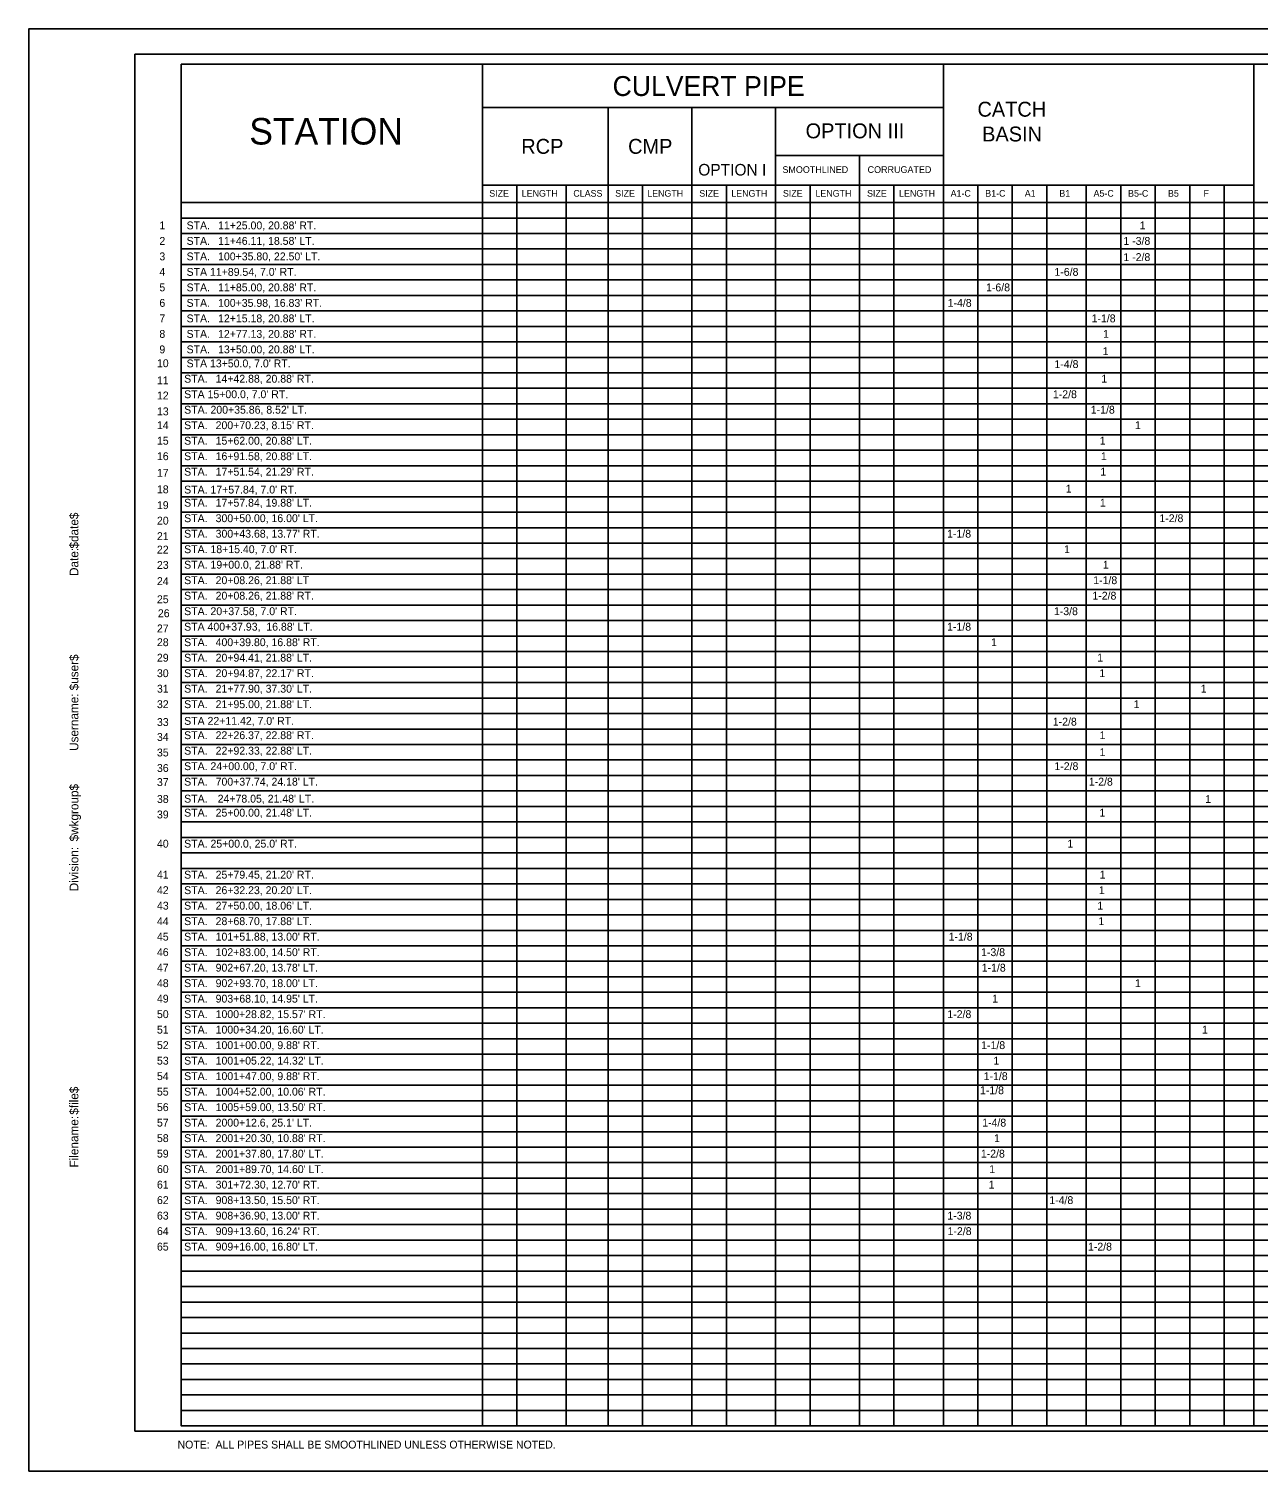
# Model space of a CAD drawing. Extents: x -0.13 to 2.7, y -0.05 to 1.78.
# Drawn here: x -0.135 to 1.428, y -0.051 to 1.782 of the extents above; entities that cross this region are included whole.
import ezdxf

# ---------------------------------------------------------------- set-up
doc = ezdxf.new("R2010")
doc.units = 0
for name, color, linetype in [('ANNOTATION', 7, 'Continuous'), ('BORDER', 7, 'Continuous'), ('PLOT BOUNDARY', 7, 'Continuous')]:
    doc.layers.add(name, color=color, linetype=linetype)

msp = doc.modelspace()

# ---------------------------------------------------------------- linework, layer by layer
at = {"layer": 'BORDER'}
for p, q in [((2.6667, 1.75), (0, 1.75)), ((0, 1.75), (0, 0)), ((0.4417, 1.6825), (0.4417, 1.7373)), ((1.0278, 1.6825), (1.0278, 1.7373)), ((1.4226, 0.0065), (1.4226, 1.7373)), ((0.4417, 1.6214), (0.4417, 1.6825)), ((0.4417, 1.6825), (0.4855, 1.6825)), ((0.4855, 1.6825), (0.5482, 1.6825)), ((0.5482, 1.6825), (0.6015, 1.6825)), ((0.6015, 1.6214), (0.6015, 1.6825)), ((0.6015, 1.6825), (0.6454, 1.6825)), ((0.6454, 1.6825), (0.7081, 1.6825)), ((0.7081, 1.6214), (0.7081, 1.6825)), ((0.7081, 1.6825), (0.7519, 1.6825)), ((0.7519, 1.6825), (0.8585, 1.6825)), ((0.8146, 1.5836), (0.8146, 1.6825)), ((0.8585, 1.6825), (1.0278, 1.6825)), ((1.0278, 1.6214), (1.0278, 1.6825)), ((0.4417, 1.5836), (0.4417, 1.6214)), ((0.6015, 1.5836), (0.6015, 1.6214)), ((0.7081, 1.5836), (0.7081, 1.6214)), ((0.8146, 1.6214), (0.8585, 1.6214)), ((0.8585, 1.6214), (0.965, 1.6214)), ((0.9212, 1.5616), (0.9212, 1.6214)), ((0.965, 1.6214), (1.0278, 1.6214)), ((1.0278, 1.5836), (1.0278, 1.6214)), ((0.4417, 1.5616), (0.4417, 1.5836)), ((0.4417, 1.5836), (0.4855, 1.5836)), ((0.4855, 1.5616), (0.4855, 1.5836)), ((0.4855, 1.5836), (0.5482, 1.5836)), ((0.5482, 1.5616), (0.5482, 1.5836)), ((0.5482, 1.5836), (0.6015, 1.5836)), ((0.6015, 1.5616), (0.6015, 1.5836)), ((0.6015, 1.5836), (0.6454, 1.5836)), ((0.6454, 1.5616), (0.6454, 1.5836)), ((0.6454, 1.5836), (0.7081, 1.5836)), ((0.7081, 1.5616), (0.7081, 1.5836)), ((0.7081, 1.5836), (0.7519, 1.5836)), ((0.7519, 1.5616), (0.7519, 1.5836)), ((0.7519, 1.5836), (0.8146, 1.5836)), ((0.8146, 1.5616), (0.8146, 1.5836)), ((0.8146, 1.5836), (0.8585, 1.5836)), ((0.8585, 1.5616), (0.8585, 1.5836)), ((0.8585, 1.5836), (0.9212, 1.5836)), ((0.9212, 1.5836), (0.965, 1.5836)), ((0.965, 1.5616), (0.965, 1.5836)), ((0.965, 1.5836), (1.0278, 1.5836)), ((1.0278, 1.5616), (1.0278, 1.5836)), ((1.0278, 1.5836), (1.0716, 1.5836)), ((1.0716, 1.5616), (1.0716, 1.5836)), ((1.0716, 1.5836), (1.1155, 1.5836)), ((1.1155, 1.5616), (1.1155, 1.5836)), ((1.1155, 1.5836), (1.1594, 1.5836)), ((1.1594, 1.5616), (1.1594, 1.5836)), ((1.1594, 1.5836), (1.1844, 1.5836)), ((1.1844, 1.5836), (1.2095, 1.5836)), ((1.2095, 1.5616), (1.2095, 1.5836)), ((1.2095, 1.5836), (1.2533, 1.5836)), ((1.2533, 1.5616), (1.2533, 1.5836)), ((1.2533, 1.5836), (1.2972, 1.5836)), ((1.2972, 1.5616), (1.2972, 1.5836)), ((1.2972, 1.5836), (1.4226, 1.5836)), ((1.3411, 1.5616), (1.3411, 1.5836)), ((1.385, 1.5616), (1.385, 1.5836)), ((0.4417, 1.5616), (0.4417, 0.0065)), ((0.4855, 1.5616), (0.4855, 0.0065)), ((0.5482, 1.5616), (0.5482, 0.0065)), ((0.6015, 1.5616), (0.6015, 0.0065)), ((0.6454, 1.5616), (0.6454, 0.0065)), ((0.7081, 1.5616), (0.7081, 0.0065)), ((0.7519, 1.5616), (0.7519, 0.0065)), ((0.8146, 1.5616), (0.8146, 0.0065)), ((0.8585, 1.5616), (0.8585, 0.0065)), ((0.9212, 1.5616), (0.9212, 0.0065)), ((0.965, 1.5616), (0.965, 0.0065)), ((1.0278, 1.5616), (1.0278, 0.0065)), ((1.0716, 1.5616), (1.0716, 0.0065)), ((1.1155, 1.5616), (1.1155, 0.0065)), ((1.1594, 1.5616), (1.1594, 0.0065)), ((1.2095, 1.5616), (1.2095, 0.0065)), ((1.2533, 1.5616), (1.2533, 0.0065)), ((1.2972, 1.5616), (1.2972, 0.0065)), ((1.3411, 1.5616), (1.3411, 0.0065)), ((1.385, 1.5616), (1.385, 0.0065)), ((0.0589, 1.5419), (2.4434, 1.5419)), ((0.0589, 1.5223), (2.4434, 1.5223)), ((0.0589, 1.5026), (2.4434, 1.5026)), ((0.0589, 1.4829), (2.4434, 1.4829)), ((0.0589, 1.4632), (2.4434, 1.4632)), ((0.0589, 1.4435), (2.4434, 1.4435)), ((0.0589, 1.4238), (2.4434, 1.4238)), ((0.0589, 1.4041), (2.4434, 1.4041)), ((0.0589, 1.3845), (2.4434, 1.3845)), ((0.0589, 1.3648), (2.4434, 1.3648)), ((0.0589, 1.3451), (2.4434, 1.3451)), ((0.0589, 1.3254), (2.4434, 1.3254)), ((0.0589, 1.3057), (2.4434, 1.3057)), ((0.0589, 1.286), (2.4434, 1.286)), ((0.0589, 1.2664), (2.4434, 1.2664)), ((0.0589, 1.2467), (2.4434, 1.2467)), ((0.0589, 1.227), (2.4434, 1.227)), ((0.0589, 1.2073), (2.4434, 1.2073)), ((0.0589, 1.1876), (2.4434, 1.1876)), ((0.0589, 1.1679), (2.4434, 1.1679)), ((0.0589, 1.1482), (2.4434, 1.1482)), ((0.0589, 1.1286), (2.4434, 1.1286)), ((0.0589, 1.1089), (2.4434, 1.1089)), ((0.0589, 1.0892), (2.4434, 1.0892)), ((0.0589, 1.0695), (2.4434, 1.0695)), ((0.0589, 1.0498), (2.4434, 1.0498)), ((0.0589, 1.0301), (2.4434, 1.0301)), ((0.0589, 1.0104), (2.4434, 1.0104)), ((0.0589, 0.9908), (2.4434, 0.9908)), ((0.0589, 0.9711), (2.4434, 0.9711)), ((0.0589, 0.9514), (2.4434, 0.9514)), ((0.0589, 0.9317), (2.4434, 0.9317)), ((0.0589, 0.912), (2.4434, 0.912)), ((0.0589, 0.8923), (2.4434, 0.8923)), ((0.0589, 0.8727), (2.4434, 0.8727)), ((0.0589, 0.853), (2.4434, 0.853)), ((0.0589, 0.8333), (2.4434, 0.8333)), ((0.0589, 0.8136), (2.4434, 0.8136)), ((0.0589, 0.7939), (2.4434, 0.7939)), ((0.0589, 0.7742), (2.4434, 0.7742)), ((0.0589, 0.7545), (2.4434, 0.7545)), ((0.0589, 0.7349), (2.4434, 0.7349)), ((0.0589, 0.7152), (2.4434, 0.7152)), ((0.0589, 0.6955), (2.4434, 0.6955)), ((0.0589, 0.6758), (2.4434, 0.6758)), ((0.0589, 0.6561), (2.4434, 0.6561)), ((0.0589, 0.6364), (2.4434, 0.6364)), ((0.0589, 0.6167), (2.4434, 0.6167)), ((0.0589, 0.5971), (2.4434, 0.5971)), ((0.0589, 0.5774), (2.4434, 0.5774)), ((0.0589, 0.5577), (2.4434, 0.5577)), ((0.0589, 0.538), (2.4434, 0.538)), ((0.0589, 0.5183), (2.4434, 0.5183)), ((0.0589, 0.4986), (2.4434, 0.4986)), ((0.0589, 0.479), (2.4434, 0.479)), ((0.0589, 0.4593), (2.4434, 0.4593)), ((0.0589, 0.4396), (2.4434, 0.4396)), ((0.0589, 0.4199), (2.4434, 0.4199)), ((0.0589, 0.4002), (2.4434, 0.4002)), ((0.0589, 0.3805), (2.4434, 0.3805)), ((0.0589, 0.3608), (2.4434, 0.3608)), ((0.0589, 0.3412), (2.4434, 0.3412)), ((0.0589, 0.3215), (2.4434, 0.3215)), ((0.0589, 0.3018), (2.4434, 0.3018)), ((0.0589, 0.2821), (2.4434, 0.2821)), ((0.0589, 0.2624), (2.4434, 0.2624)), ((0.0589, 0.2427), (2.4434, 0.2427)), ((0.0589, 0.223), (2.4434, 0.223)), ((0.0589, 0.2034), (2.4434, 0.2034)), ((0.0589, 0.1837), (2.4434, 0.1837)), ((0.0589, 0.164), (2.4434, 0.164)), ((0.0589, 0.1443), (2.4434, 0.1443)), ((0.0589, 0.1246), (2.4434, 0.1246)), ((0.0589, 0.1049), (2.4434, 0.1049)), ((0.0589, 0.0853), (2.4434, 0.0853)), ((0.0589, 0.0656), (2.4434, 0.0656)), ((0.0589, 0.0459), (2.4434, 0.0459)), ((0.0589, 0.0262), (2.4434, 0.0262)), ((0, 0), (2.6667, 0)), ((0.0589, 0.0065), (2.3003, 0.0065))]:
    msp.add_line(p, q, dxfattribs=at)
msp.add_lwpolyline([(0.0589, 1.7373), (2.4434, 1.7373), (2.4434, 1.5616), (0.0589, 1.5616)], close=True, dxfattribs=at)
msp.add_lwpolyline([(0.0589, 1.5616), (0.0589, 0.0065), (2.4434, 0.0065), (2.4434, 1.5616)], dxfattribs=at)
at = {"layer": 'PLOT BOUNDARY'}
msp.add_lwpolyline([(-0.1349, -0.051), (2.6984, -0.051), (2.6984, 1.7823), (-0.1349, 1.7823)], close=True, dxfattribs=at)

# ---------------------------------------------------------------- texts
at = {"layer": 'ANNOTATION'}
for s, p in [('1', (0.0311, 1.5275)), ('STA.', (0.0657, 1.5275)), ("11+25.00, 20.88' RT.", (0.1057, 1.5275)), ('1', (1.2774, 1.5275)), ('2', (0.0311, 1.5078)), ('STA.', (0.0657, 1.5078)), ("11+46.11, 18.58' LT.", (0.1057, 1.5078)), ('1 -3/8', (1.2567, 1.5078)), ('3', (0.0311, 1.4881)), ('STA.', (0.0657, 1.4881)), ("100+35.80, 22.50' LT.", (0.1057, 1.4881)), ('1 -2/8', (1.2567, 1.4872)), ('4', (0.0311, 1.4684)), ("STA 11+89.54, 7.0' RT.", (0.0657, 1.4684)), ('1-6/8', (1.1691, 1.4684)), ('5', (0.0311, 1.4487)), ('STA.', (0.0657, 1.4487)), ("11+85.00, 20.88' RT.", (0.1057, 1.4487)), ('1-6/8', (1.0821, 1.4487)), ('6', (0.0311, 1.429)), ('STA.', (0.0657, 1.429)), ("100+35.98, 16.83' RT.", (0.1057, 1.429)), ('1-4/8', (1.0333, 1.429)), ('7', (0.0311, 1.4093)), ('STA.', (0.0657, 1.4093)), ("12+15.18, 20.88' LT.", (0.1057, 1.4093)), ('1-1/8', (1.2163, 1.4093)), ('8', (0.0311, 1.3896)), ('STA.', (0.0657, 1.3896)), ("12+77.13, 20.88' RT.", (0.1057, 1.3896)), ('1', (1.2309, 1.3896)), ('9', (0.0311, 1.3699)), ('STA.', (0.0657, 1.3699)), ("13+50.00, 20.88' LT.", (0.1057, 1.3699)), ('1', (1.2304, 1.3677)), ('10', (0.028, 1.3523)), ("STA 13+50.0, 7.0' RT.", (0.0657, 1.3521)), ('1-4/8', (1.1691, 1.3512)), ('11', (0.028, 1.3305)), ('STA.', (0.0626, 1.3326)), ("14+42.88, 20.88' RT.", (0.1026, 1.3326)), ('1', (1.2286, 1.3326)), ('12', (0.028, 1.3113)), ("STA 15+00.0, 7.0' RT.", (0.0626, 1.3129)), ('1-2/8', (1.1671, 1.3129)), ("STA. 200+35.86, 8.52' LT.", (0.0626, 1.2932)), ('1-1/8', (1.2153, 1.2932)), ('13', (0.028, 1.2911)), ('14', (0.028, 1.2735)), ('STA.', (0.0626, 1.2735)), ("200+70.23, 8.15' RT.", (0.1026, 1.2735)), ('1', (1.2715, 1.2735)), ('15', (0.028, 1.2538)), ('STA.', (0.0626, 1.2538)), ("15+62.00, 20.88' LT.", (0.1026, 1.2538)), ('1', (1.2266, 1.2538)), ('16', (0.028, 1.2341)), ('STA.', (0.0626, 1.2341)), ("16+91.58, 20.88' LT.", (0.1026, 1.2341)), ('1', (1.2281, 1.2341)), ('17', (0.028, 1.213)), ('STA.', (0.0626, 1.2144)), ("17+51.54, 21.29' RT.", (0.1026, 1.2144)), ('1', (1.2274, 1.2144)), ('18', (0.028, 1.192)), ("STA. 17+57.84, 7.0' RT.", (0.0626, 1.1917)), ('1', (1.1834, 1.1928)), ('19', (0.028, 1.1719)), ('STA.', (0.0626, 1.175)), ("17+57.84, 19.88' LT.", (0.1026, 1.175)), ('1', (1.2268, 1.175)), ('20', (0.028, 1.1522)), ('STA.', (0.0626, 1.1553)), ("300+50.00, 16.00' LT.", (0.1026, 1.1553)), ('1-2/8', (1.3025, 1.1553)), ('21', (0.028, 1.1325)), ('STA.', (0.0626, 1.1356)), ("300+43.68, 13.77' RT.", (0.1026, 1.1356)), ('1-1/8', (1.0326, 1.1356)), ('22', (0.028, 1.1154)), ("STA. 18+15.40, 7.0' RT.", (0.0626, 1.1159)), ('1', (1.1813, 1.1159)), ('23', (0.028, 1.0959)), ("STA. 19+00.0, 21.88' RT.", (0.0626, 1.0962)), ('1', (1.2306, 1.0962)), ('24', (0.028, 1.0753)), ('STA.', (0.0626, 1.0765)), ("20+08.26, 21.88' LT", (0.1026, 1.0765)), ('1-1/8', (1.2184, 1.0765)), ('STA.', (0.0626, 1.0568)), ("20+08.26, 21.88' RT.", (0.1026, 1.0568)), ('1-2/8', (1.2173, 1.0568)), ('25', (0.028, 1.0523)), ("STA. 20+37.58, 7.0' RT.", (0.0626, 1.0371)), ('1-3/8', (1.1684, 1.0371)), ('26', (0.0292, 1.0345)), ("STA 400+37.93,  16.88' LT.", (0.0626, 1.0174)), ('1-1/8', (1.0326, 1.0174)), ('27', (0.028, 1.0152)), ('28', (0.028, 0.9977)), ('STA.', (0.0626, 0.9977)), ("400+39.80, 16.88' RT.", (0.1026, 0.9977)), ('1', (1.0885, 0.9977)), ('29', (0.028, 0.978)), ('STA.', (0.0626, 0.978)), ("20+94.41, 21.88' LT.", (0.1026, 0.978)), ('1', (1.2234, 0.978)), ('30', (0.028, 0.9583)), ('STA.', (0.0626, 0.9583)), ("20+94.87, 22.17' RT.", (0.1026, 0.9583)), ('1', (1.2261, 0.9583)), ('31', (0.028, 0.9386)), ('STA.', (0.0626, 0.9386)), ("21+77.90, 37.30' LT.", (0.1026, 0.9386)), ('1', (1.355, 0.9386)), ('32', (0.028, 0.9189)), ('STA.', (0.0626, 0.9189)), ("21+95.00, 21.88' LT.", (0.1026, 0.9189)), ('1', (1.2698, 0.9189)), ('33', (0.028, 0.8962)), ("STA 22+11.42, 7.0' RT.", (0.0626, 0.8977)), ('1-2/8', (1.167, 0.8967)), ('34', (0.028, 0.8772)), ('STA.', (0.0626, 0.8795)), ("22+26.37, 22.88' RT.", (0.1026, 0.8795)), ('1', (1.2264, 0.8795)), ('35', (0.028, 0.8575)), ('STA.', (0.0626, 0.8598)), ("22+92.33, 22.88' LT.", (0.1026, 0.8598)), ('1', (1.2264, 0.8579)), ('36', (0.028, 0.8378)), ("STA. 24+00.00, 7.0' RT.", (0.0626, 0.8401)), ('1-2/8', (1.169, 0.8401)), ('37', (0.028, 0.8199)), ('STA.', (0.0626, 0.8204)), ("700+37.74, 24.18' LT.", (0.1026, 0.8204)), ('1-2/8', (1.2128, 0.8204)), ('38', (0.028, 0.7984)), ('STA.', (0.0626, 0.7988)), ("24+78.05, 21.48' LT.", (0.1052, 0.7988)), ('1', (1.3607, 0.7983)), ('39', (0.028, 0.7787)), ('STA.', (0.0626, 0.781)), ("25+00.00, 21.48' LT.", (0.1026, 0.781)), ('1', (1.2262, 0.781)), ('40', (0.028, 0.7416)), ("STA. 25+00.0, 25.0' RT.", (0.0626, 0.7416)), ('1', (1.1855, 0.7416)), ('41', (0.028, 0.7022)), ('STA.', (0.0626, 0.7022)), ("25+79.45, 21.20' RT.", (0.1026, 0.7022)), ('1', (1.2265, 0.7022)), ('42', (0.028, 0.6825)), ('STA.', (0.0626, 0.6825)), ("26+32.23, 20.20' LT.", (0.1026, 0.6825)), ('1', (1.2255, 0.6825)), ('43', (0.028, 0.6628)), ('STA.', (0.0626, 0.6628)), ("27+50.00, 18.06' LT.", (0.1026, 0.6628)), ('1', (1.2236, 0.6628)), ('44', (0.028, 0.6431)), ('STA.', (0.0626, 0.6431)), ("28+68.70, 17.88' LT.", (0.1026, 0.6431)), ('1', (1.2249, 0.6431)), ('45', (0.028, 0.6234)), ('STA.', (0.0626, 0.6234)), ("101+51.88, 13.00' RT.", (0.1026, 0.6234)), ('1-1/8', (1.0345, 0.6234)), ('46', (0.028, 0.6037)), ('STA.', (0.0626, 0.6037)), ("102+83.00, 14.50' RT.", (0.1026, 0.6037)), ('1-3/8', (1.0758, 0.6037)), ('47', (0.028, 0.584)), ('STA.', (0.0626, 0.584)), ("902+67.20, 13.78' LT.", (0.1026, 0.584)), ('1-1/8', (1.0766, 0.584)), ('48', (0.028, 0.5643)), ('STA.', (0.0626, 0.5643)), ("902+93.70, 18.00' LT.", (0.1026, 0.5643)), ('1', (1.2715, 0.5643)), ('49', (0.028, 0.5446)), ('STA.', (0.0626, 0.5446)), ("903+68.10, 14.95' LT.", (0.1026, 0.5446)), ('1', (1.0899, 0.5446)), ('50', (0.028, 0.5249)), ('STA.', (0.0626, 0.5249)), ("1000+28.82, 15.57' RT.", (0.1026, 0.5249)), ('1-2/8', (1.0329, 0.5249)), ('51', (0.028, 0.5052)), ('STA.', (0.0626, 0.5052)), ("1000+34.20, 16.60' LT.", (0.1026, 0.5052)), ('1', (1.3566, 0.5052)), ('52', (0.028, 0.4855)), ('STA.', (0.0626, 0.4855)), ("1001+00.00, 9.88' RT.", (0.1026, 0.4855)), ('1-1/8', (1.0759, 0.4855)), ('53', (0.028, 0.4658)), ('STA.', (0.0626, 0.4658)), ("1001+05.22, 14.32' LT.", (0.1026, 0.4658)), ('1', (1.0914, 0.4658)), ('54', (0.028, 0.4461)), ('STA.', (0.0626, 0.4461)), ("1001+47.00, 9.88' RT.", (0.1026, 0.4461)), ('1-1/8', (1.0791, 0.4461)), ('55', (0.028, 0.4264)), ('STA.', (0.0626, 0.4264)), ("1004+52.00, 10.06' RT.", (0.1026, 0.4264)), ('1-1/8', (1.0744, 0.4282)), ('56', (0.028, 0.4067)), ('STA.', (0.0626, 0.4067)), ("1005+59.00, 13.50' RT.", (0.1026, 0.4067)), ('57', (0.028, 0.387)), ('STA.', (0.0626, 0.387)), ("2000+12.6, 25.1' LT.", (0.1026, 0.387)), ('1-4/8', (1.0772, 0.387)), ('58', (0.028, 0.3673)), ('STA.', (0.0626, 0.3673)), ("2001+20.30, 10.88' RT.", (0.1026, 0.3673)), ('1', (1.0924, 0.3673)), ('59', (0.028, 0.3476)), ('STA.', (0.0626, 0.3476)), ("2001+37.80, 17.80' LT.", (0.1026, 0.3476)), ('1-2/8', (1.0755, 0.3476)), ('60', (0.028, 0.3279)), ('STA.', (0.0626, 0.3279)), ("2001+89.70, 14.60' LT.", (0.1026, 0.3279)), ('1', (1.0861, 0.3279)), ('61', (0.028, 0.3082)), ('STA.', (0.0626, 0.3082)), ("301+72.30, 12.70' RT.", (0.1026, 0.3082)), ('1', (1.0854, 0.3082)), ('62', (0.028, 0.2885)), ('STA.', (0.0626, 0.2885)), ("908+13.50, 15.50' RT.", (0.1026, 0.2885)), ('1-4/8', (1.1625, 0.2885)), ('63', (0.028, 0.2688)), ('STA.', (0.0626, 0.2688)), ("908+36.90, 13.00' RT.", (0.1026, 0.2688)), ('1-3/8', (1.0329, 0.2688)), ('64', (0.028, 0.2491)), ('STA.', (0.0626, 0.2491)), ("909+13.60, 16.24' RT.", (0.1026, 0.2491)), ('1-2/8', (1.0332, 0.2491)), ('65', (0.028, 0.2294)), ('STA.', (0.0626, 0.2294)), ("909+16.00, 16.80' LT.", (0.1026, 0.2294)), ('1-2/8', (1.2117, 0.2294)), ('NOTE:  ALL PIPES SHALL BE SMOOTHLINED UNLESS OTHERWISE NOTED.', (0.0542, -0.0222))]:
    msp.add_text(s, height=0.01, dxfattribs=at).set_placement(p)
at = {"layer": 'BORDER'}
for s, height, p in [('CULVERT PIPE', 0.025276, (0.6073, 1.697)), ('CATCH', 0.01896, (1.0712, 1.6707)), ('STATION', 0.0337, (0.1454, 1.6353)), ('OPTION III', 0.01896, (0.8527, 1.6432)), ('BASIN', 0.01896, (1.0771, 1.6392)), ('RCP', 0.01896, (0.4912, 1.6235)), ('CMP', 0.01896, (0.627, 1.6235)), ('OPTION I', 0.01474, (0.7162, 1.5959)), ('SMOOTHLINED', 0.008531, (0.8232, 1.5992)), ('CORRUGATED', 0.00853, (0.9315, 1.5992)), ('SIZE', 0.00843, (0.4505, 1.569)), ('LENGTH', 0.00843, (0.4918, 1.569)), ('CLASS', 0.00843, (0.5574, 1.569)), ('SIZE', 0.00843, (0.6106, 1.569)), ('LENGTH', 0.00843, (0.6513, 1.569)), ('SIZE', 0.00843, (0.7175, 1.569)), ('LENGTH', 0.00843, (0.7582, 1.569)), ('SIZE', 0.00843, (0.8238, 1.569)), ('LENGTH', 0.00843, (0.8652, 1.569)), ('SIZE', 0.00843, (0.9308, 1.569)), ('LENGTH', 0.00843, (0.9715, 1.569)), ('A1-C', 0.00843, (1.0371, 1.569)), ('B1-C', 0.00843, (1.0811, 1.569)), ('A1', 0.00843, (1.1313, 1.569)), ('B1', 0.00843, (1.1753, 1.569)), ('A5-C', 0.00843, (1.2188, 1.569)), ('B5-C', 0.00843, (1.2627, 1.569)), ('B5', 0.00843, (1.3134, 1.569)), ('F', 0.00843, (1.3585, 1.569))]:
    msp.add_text(s, height=height, dxfattribs=at).set_placement(p)
for s, p in [('$date$', (-0.0719, 1.1218)), ('Date:', (-0.0719, 1.0869)), ('$user$', (-0.0719, 0.9415)), ('Username:', (-0.0719, 0.8645)), ('$wkgroup$', (-0.0719, 0.7495)), ('Division:', (-0.0719, 0.6861)), ('$file$', (-0.0719, 0.4021)), ('Filename:', (-0.0719, 0.335))]:
    msp.add_text(s, height=0.01116, rotation=90, dxfattribs=at).set_placement(p)

doc.saveas('drawing.dxf')
